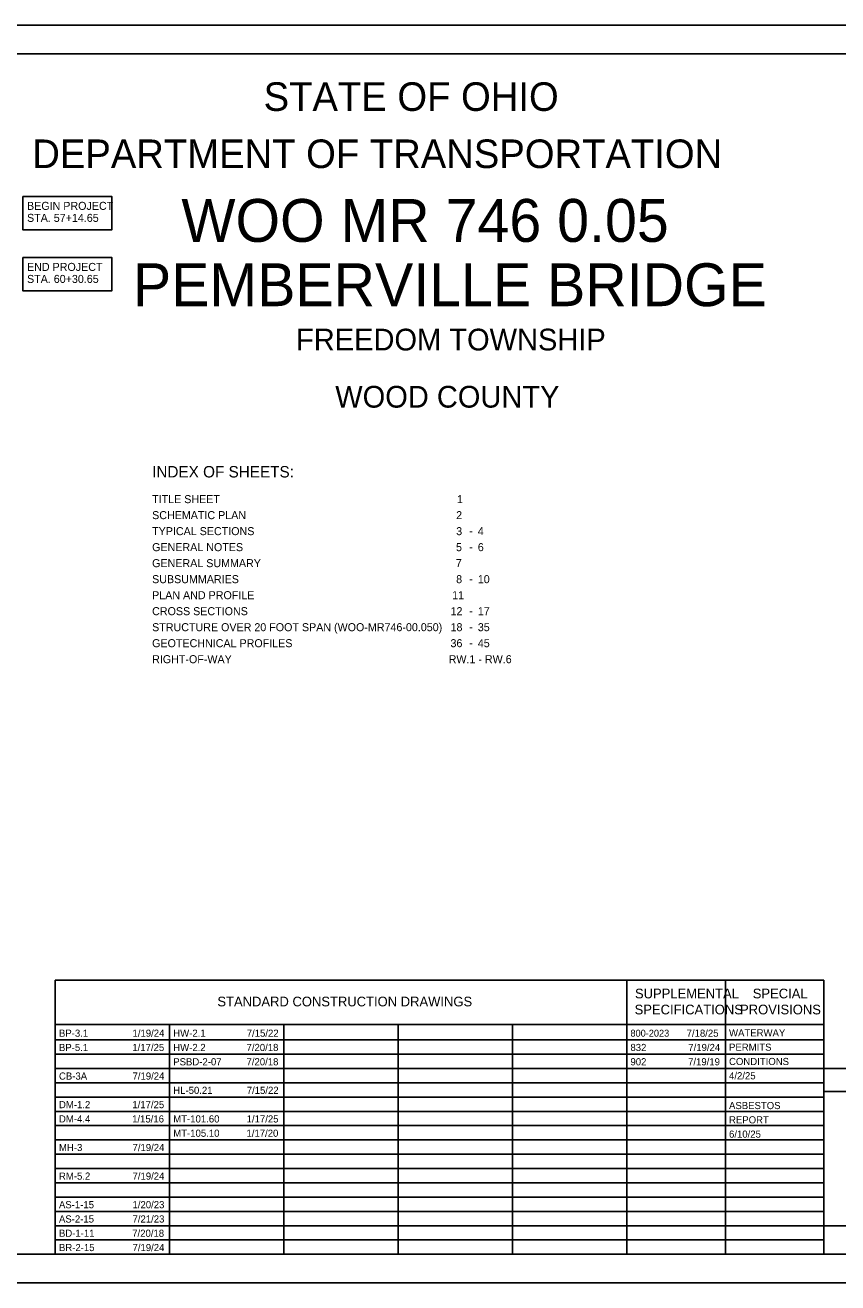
# Model space of a CAD drawing. Extents: x -8.3 to 42.1, y 0 to 22.
# Drawn here: x 9.62 to 23.84, y 0 to 22 of the extents above; entities that cross this region are included whole.
import ezdxf

# ---------------------------------------------------------------- set-up
doc = ezdxf.new("R2010")
doc.units = 0
for name, color, linetype in [('SH_Border', 7, 'Continuous'), ('SH_Cut_Line', 7, 'Continuous'), ('SH_Data', 7, 'Continuous'), ('SH_Text', 7, 'Continuous')]:
    doc.layers.add(name, color=color, linetype=linetype)

msp = doc.modelspace()

# ---------------------------------------------------------------- linework, layer by layer
at = {"layer": 'SH_Border'}
msp.add_lwpolyline([(1.5, 21.5), (33.5, 21.5), (33.5, 0.5), (1.5, 0.5)], close=True, dxfattribs=at)
at = {"layer": 'SH_Cut_Line'}
msp.add_lwpolyline([(0, 0), (34, 0), (34, 22), (0, 22)], close=True, dxfattribs=at)
at = {"layer": 'SH_Data'}
for p, q in [((10.15, 5.292), (23.6, 5.292)), ((10.15, 0.5), (10.15, 5.292)), ((20.15, 0.5), (20.15, 5.292)), ((21.875, 0.5), (21.875, 5.292)), ((23.6, 0.5), (23.6, 5.292)), ((10.15, 4.521), (23.6, 4.521)), ((12.15, 0.5), (12.15, 4.521)), ((14.15, 0.5), (14.15, 4.521)), ((16.15, 0.5), (16.15, 4.521)), ((18.15, 0.5), (18.15, 4.521)), ((10.15, 4.25), (23.6, 4.25)), ((10.15, 4), (23.6, 4)), ((10.15, 3.75), (23.6, 3.75)), ((23.6, 0.5), (23.6, 3.75)), ((23.6, 3.75), (26.4, 3.75)), ((10.15, 3.5), (23.6, 3.5)), ((23.6, 3.35), (26.4, 3.35)), ((10.15, 3.25), (23.6, 3.25)), ((10.15, 3), (23.6, 3)), ((10.15, 2.75), (23.6, 2.75)), ((10.15, 2.5), (23.6, 2.5)), ((10.15, 2.25), (23.6, 2.25)), ((10.15, 2), (23.6, 2)), ((10.15, 1.75), (23.6, 1.75)), ((10.15, 1.5), (23.6, 1.5)), ((10.15, 1.25), (23.6, 1.25)), ((10.15, 1), (23.6, 1)), ((10.15, 0.75), (23.6, 0.75)), ((23.6, 0.5), (26.4, 0.5))]:
    msp.add_line(p, q, dxfattribs=at)
msp.add_lwpolyline([(23.6, 0.5), (23.6, 1), (26.4, 1), (26.4, 0.5)], close=True, dxfattribs=at)
at = {"layer": 'SH_Text'}
for points in [[(9.581, 19.002), (11.14, 19.002), (11.14, 18.421), (9.581, 18.421)], [(9.581, 17.934), (11.14, 17.934), (11.14, 17.353), (9.581, 17.353)]]:
    msp.add_lwpolyline(points, close=True, dxfattribs=at)

# ---------------------------------------------------------------- texts
for s, height, p in [('STATE OF OHIO', 0.5, (13.795, 20.5)), ('DEPARTMENT OF TRANSPORTATION', 0.5, (9.747, 19.5)), ('WOO MR 746 0.05', 0.75, (12.356, 18.209)), ('STA. 57+14.65', 0.14, (9.655, 18.559)), ('BEGIN PROJECT', 0.14, (9.655, 18.769)), ('END PROJECT', 0.14, (9.655, 17.701)), ('PEMBERVILLE BRIDGE ', 0.75, (11.509, 17.084)), ('STA. 60+30.65', 0.14, (9.655, 17.491)), ('FREEDOM TOWNSHIP', 0.38, (14.362, 16.31)), ('WOOD COUNTY ', 0.38, (15.048, 15.31)), ('INDEX OF SHEETS:', 0.2, (11.844, 14.088)), ('TITLE SHEET', 0.14, (11.844, 13.639)), ('1', 0.14, (17.179, 13.639)), ('SCHEMATIC PLAN', 0.14, (11.844, 13.359)), ('2', 0.14, (17.164, 13.359)), ('TYPICAL SECTIONS', 0.14, (11.844, 13.079)), ('3', 0.14, (17.165, 13.079)), ('4', 0.14, (17.543, 13.079)), ('-', 0.14, (17.395, 13.083)), ('GENERAL NOTES', 0.14, (11.844, 12.799)), ('5', 0.14, (17.162, 12.799)), ('-', 0.14, (17.395, 12.803)), ('6', 0.14, (17.543, 12.799)), ('GENERAL SUMMARY', 0.14, (11.844, 12.519)), ('7', 0.14, (17.158, 12.519)), ('SUBSUMMARIES', 0.14, (11.844, 12.239)), ('8', 0.14, (17.164, 12.239)), ('10', 0.14, (17.543, 12.239)), ('PLAN AND PROFILE', 0.14, (11.844, 11.959)), ('-', 0.14, (17.395, 12.243)), ('11', 0.14, (17.094, 11.959)), ('CROSS SECTIONS', 0.14, (11.844, 11.679)), ('12', 0.14, (17.066, 11.679)), ('-', 0.14, (17.395, 11.683)), ('17', 0.14, (17.543, 11.679)), ('STRUCTURE OVER 20 FOOT SPAN (WOO-MR746-00.050)', 0.14, (11.844, 11.399)), ('18', 0.14, (17.066, 11.399)), ('-', 0.14, (17.395, 11.403)), ('35', 0.14, (17.543, 11.399)), ('GEOTECHNICAL PROFILES', 0.14, (11.844, 11.119)), ('36', 0.14, (17.065, 11.119)), ('45', 0.14, (17.543, 11.119)), ('-', 0.14, (17.395, 11.123)), ('RIGHT-OF-WAY', 0.14, (11.844, 10.839)), ('RW.1 - RW.6', 0.14, (17.033, 10.839)), ('SUPPLEMENTAL', 0.17, (20.293, 4.976)), ('SPECIAL', 0.17, (22.354, 4.976)), ('STANDARD CONSTRUCTION DRAWINGS', 0.17, (12.986, 4.836)), ('SPECIFICATIONS', 0.17, (20.287, 4.696)), ('PROVISIONS', 0.17, (22.132, 4.696)), ('BP-3.1', 0.125, (10.214, 4.305)), ('1/19/24', 0.125, (11.501, 4.305)), ('HW-2.1', 0.125, (12.214, 4.305)), ('7/15/22', 0.125, (13.5, 4.305)), ('800-2023', 0.12, (20.214, 4.307)), ('7/18/25', 0.125, (21.197, 4.305)), ('WATERWAY', 0.125, (21.939, 4.31)), ('1/17/25', 0.125, (11.498, 4.055)), ('HW-2.2', 0.125, (12.214, 4.055)), ('7/20/18', 0.125, (13.496, 4.055)), ('832', 0.125, (20.214, 4.055)), ('7/19/24', 0.125, (21.226, 4.055)), ('PERMITS', 0.125, (21.939, 4.06)), ('BP-5.1', 0.125, (10.214, 4.055)), ('PSBD-2-07', 0.125, (12.214, 3.805)), ('7/20/18', 0.125, (13.496, 3.805)), ('902', 0.125, (20.214, 3.805)), ('7/19/19', 0.125, (21.222, 3.805)), ('CONDITIONS', 0.125, (21.939, 3.81)), ('CB-3A', 0.125, (10.214, 3.555)), ('7/19/24', 0.125, (11.501, 3.555)), ('4/2/25', 0.125, (21.939, 3.56)), ('HL-50.21', 0.125, (12.214, 3.305)), ('7/15/22', 0.125, (13.5, 3.305)), ('DM-1.2', 0.125, (10.214, 3.055)), ('1/17/25', 0.125, (11.498, 3.055)), ('ASBESTOS', 0.125, (21.939, 3.039)), ('DM-4.4', 0.125, (10.214, 2.805)), ('1/15/16', 0.125, (11.494, 2.805)), ('MT-101.60', 0.125, (12.214, 2.805)), ('1/17/25', 0.125, (13.498, 2.805)), ('REPORT', 0.125, (21.939, 2.789)), ('MT-105.10', 0.125, (12.214, 2.555)), ('1/17/20', 0.125, (13.495, 2.555)), ('6/10/25', 0.125, (21.939, 2.539)), ('MH-3', 0.125, (10.214, 2.305)), ('7/19/24', 0.125, (11.501, 2.305)), ('RM-5.2', 0.125, (10.214, 1.805)), ('7/19/24', 0.125, (11.501, 1.805)), ('AS-1-15', 0.125, (10.214, 1.305)), ('1/20/23', 0.125, (11.501, 1.305)), ('AS-2-15', 0.125, (10.214, 1.055)), ('7/21/23', 0.125, (11.501, 1.055)), ('BD-1-11', 0.125, (10.214, 0.805)), ('7/20/18', 0.125, (11.496, 0.805)), ('BR-2-15', 0.125, (10.214, 0.555)), ('7/19/24', 0.125, (11.501, 0.555))]:
    msp.add_text(s, height=height, dxfattribs=at).set_placement(p)

doc.saveas('drawing.dxf')
